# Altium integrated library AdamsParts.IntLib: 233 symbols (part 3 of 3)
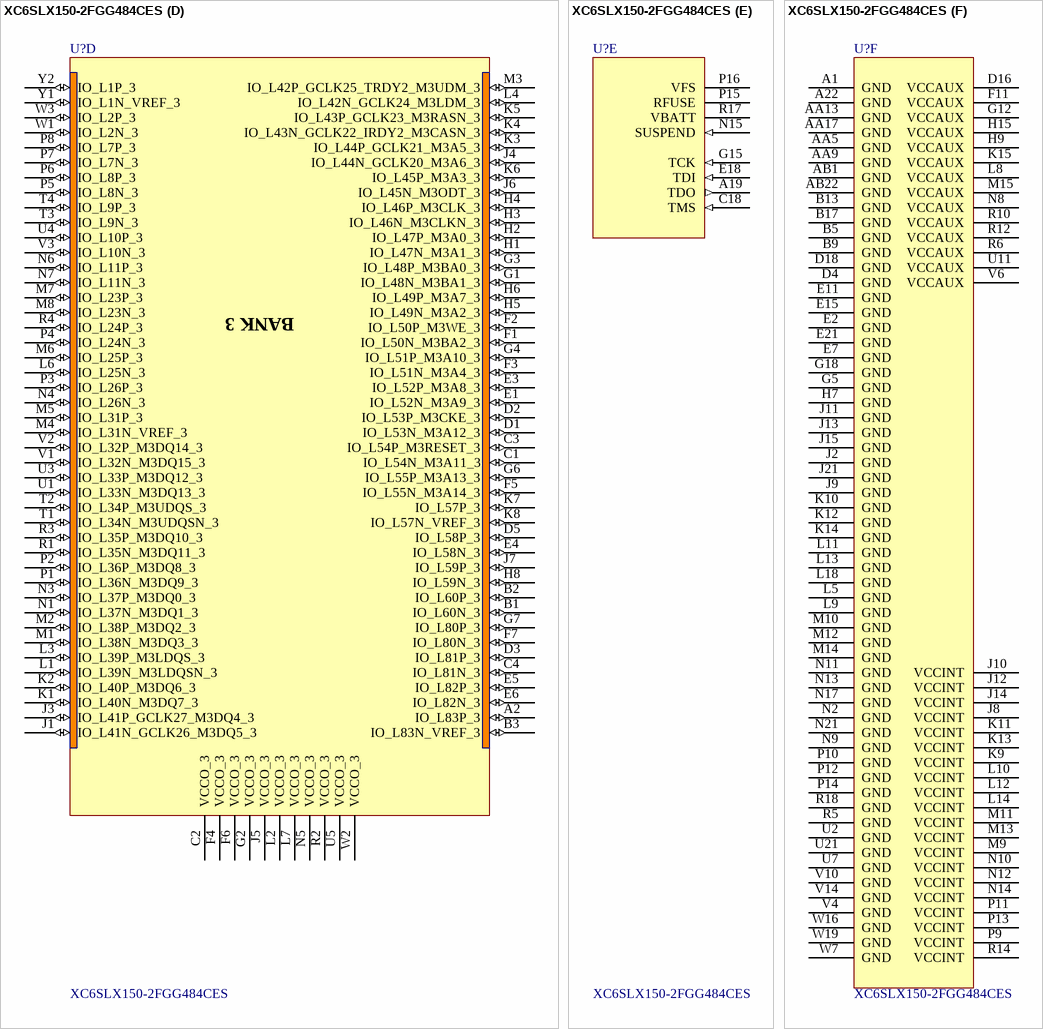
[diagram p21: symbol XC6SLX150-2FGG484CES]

## XC6SLX150-2FGG484CES
designator U?
Spartan 6 LX150 FGG484; Manufacturer: Xilinx
footprint FGG484 (BGA, 484-Leads, Body 23x23mm, Pitch 1mm)
part A pins: A3 IO_L1P_HSWAPEN_0 (io), A4 IO_L1N_VREF_0 (io), A5 IO_L2N_0 (io), A6 IO_L4N_0 (io), A7 IO_L5N_0 (io), A8 IO_L6N_0 (io), A9 IO_L8N_VREF_0 (io), A10 IO_L34N_GCLK18_0 (io), A11 IO_L35N_GCLK16_0 (io), A12 IO_L37N_GCLK12_0 (io), A13 IO_L38N_VREF_0 (io), A14 IO_L50N_0 (io), A15 IO_L51N_0 (io), A16 IO_L63N_SCP6_0 (io), A17 IO_L64N_SCP4_0 (io), A18 IO_L65N_SCP2_0 (io), B4 VCCO_0 (power), B6 IO_L4P_0 (io), B7 VCCO_0 (power), B8 IO_L6P_0 (io), B10 IO_L34P_GCLK19_0 (io), B11 VCCO_0 (power), B12 IO_L37P_GCLK13_0 (io), B14 IO_L50P_0 (io), B15 VCCO_0 (power), B16 IO_L63P_SCP7_0 (io), B18 IO_L65P_SCP3_0 (io), B19 VCCO_0 (power), C5 IO_L2P_0 (io), C6 IO_L3N_0 (io), C7 IO_L5P_0 (io), C8 IO_L7N_0 (io), C9 IO_L8P_0 (io), C10 IO_L33N_0 (io), C11 IO_L35P_GCLK17_0 (io), C12 IO_L36N_GCLK14_0 (io), C13 IO_L38P_0 (io), C14 IO_L49N_0 (io), C15 IO_L51P_0 (io), C16 IO_L62N_VREF_0 (io), C17 IO_L64P_SCP5_0 (io), D6 IO_L3P_0 (io), D7 IO_L32P_0 (io), D8 IO_L32N_0 (io), D9 IO_L7P_0 (io), D10 IO_L33P_0 (io), D11 IO_L36P_GCLK15_0 (io), D12 IO_L43N_0_AVOID (io), D13 IO_L45N_0_AVOID (io), D14 IO_L49P_0 (io), D15 IO_L62P_0 (io), D17 IO_L66N_SCP0_0 (io), E8 IO_L14P_0_AVOID (io), E9 VCCO_0 (power), E10 IO_L17P_0_AVOID (io), E12 IO_L43P_0_AVOID (io), E13 VCCO_0 (power), E14 IO_L47P_0_AVOID (io), E16 IO_L66P_SCP1_0 (io), E17 VCCO_0 (power), F8 IO_L14N_0_AVOID (io), F9 IO_L15N_0_AVOID (io), F10 IO_L17N_0_AVOID (io), F12 IO_L44N_0_AVOID (io), F13 IO_L45P_0_AVOID (io), F14 IO_L48P_0_AVOID (io), F15 IO_L47N_0_AVOID (io), G8 IO_L15P_0_AVOID (io), G9 IO_L16P_0_AVOID (io), G10 VCCO_0 (power), G11 IO_L18P_0_AVOID (io), G13 IO_L46N_0_AVOID (io), G14 VCCO_0 (power), H10 IO_L16N_0_AVOID (io), H11 IO_L18N_0_AVOID (io), H12 IO_L44P_0_AVOID (io), H13 IO_L46P_0_AVOID (io), H14 IO_L48N_0_AVOID (io)
part B pins: A20 IO_L20P_1 (io), A21 IO_L20N_1 (io), B20 IO_L1N_A24_VREF_1 (io), B21 IO_L19P_1 (io), B22 IO_L19N_1 (io), C19 IO_L1P_A25_1 (io), C20 IO_L32P_A17_M1A8_1 (io), C21 VCCO_1 (power), C22 IO_L32N_A16_M1A9_1 (io), D19 IO_L29P_A23_M1A13_1 (io), D20 IO_L29N_A22_M1A14_1 (io), D21 IO_L31P_A19_M1CKE_1 (io), D22 IO_L31N_A18_M1A12_1 (io), E19 VCCO_1 (power), E20 IO_L35P_A11_M1A7_1 (io), E22 IO_L35N_A10_M1A2_1 (io), F16 IO_L10P_1 (io), F17 IO_L10N_1 (io), F18 IO_L30P_A21_M1RESET_1 (io), F19 IO_L30N_A20_M1A11_1 (io), F20 IO_L33N_A14_M1A4_1 (io), F21 IO_L37P_A7_M1A0_1 (io), F22 IO_L37N_A6_M1A1_1 (io), G16 IO_L9P_1 (io), G17 IO_L9N_1 (io), G19 IO_L33P_A15_M1A10_1 (io), G20 IO_L39P_M1A3_1 (io), G21 VCCO_1 (power), G22 IO_L39N_M1ODT_1 (io), H16 IO_L28P_1 (io), H17 IO_L28N_VREF_1 (io), H18 IO_L34N_A12_M1BA2_1 (io), H19 IO_L34P_A13_M1WE_1 (io), H20 IO_L38P_A5_M1CLK_1 (io), H21 IO_L41P_GCLK9_IRDY1_M1RASN_1 (io), H22 IO_L41N_GCLK8_M1CASN_1 (io), J16 IO_L21N_1 (io), J17 IO_L36P_A9_M1BA0_1 (io), J18 VCCO_1 (power), J19 IO_L38N_A4_M1CLKN_1 (io), J20 IO_L43P_GCLK5_M1DQ4_1 (io), J22 IO_L43N_GCLK4_M1DQ5_1 (io), K16 IO_L21P_1 (io), K17 IO_L36N_A8_M1BA1_1 (io), K18 IO_L61N_1 (io), K19 IO_L40N_GCLK10_M1A6_1 (io), K20 IO_L40P_GCLK11_M1A5_1 (io), K21 IO_L44P_A3_M1DQ6_1 (io), K22 IO_L44N_A2_M1DQ7_1 (io), L15 IO_L58N_1 (io), L16 VCCO_1 (power), L17 IO_L61P_1 (io), L19 IO_L42N_GCLK6_TRDY1_M1LDM_1 (io), L20 IO_L45P_A1_M1LDQS_1 (io), L21 VCCO_1 (power), L22 IO_L45N_A0_M1LDQSN_1 (io), M16 IO_L58P_1 (io), M17 IO_L71P_1 (io), M18 IO_L71N_1 (io), M19 IO_L53P_1 (io), M20 IO_L42P_GCLK7_M1UDM_1 (io), M21 IO_L46P_FCS_B_M1DQ2_1 (io), M22 IO_L46N_FOE_B_M1DQ3_1 (io), N16 IO_L72N_1 (io), N18 VCCO_1 (power), N19 IO_L53N_VREF_1 (io), N20 IO_L47P_FWE_B_M1DQ0_1 (io), N22 IO_L47N_LDC_M1DQ1_1 (io), P17 IO_L72P_1 (io), P18 IO_L73P_1 (io), P19 IO_L59P_1 (io), P20 IO_L59N_1 (io), P21 IO_L48P_HDC_M1DQ8_1 (io), P22 IO_L48N_M1DQ9_1 (io), R19 IO_L73N_1 (io), R20 IO_L49P_M1DQ10_1 (io), R21 VCCO_1 (power), R22 IO_L49N_M1DQ11_1 (io), T19 IO_L74P_AWAKE_1 (io), T20 IO_L74N_DOUT_BUSY_1 (io), T21 IO_L50P_M1UDQS_1 (io), T22 IO_L50N_M1UDQSN_1 (io), U18 VCCO_1 (power), U19 IO_L70P_1 (io), U20 IO_L51P_M1DQ12_1 (io), U22 IO_L51N_M1DQ13_1 (io), V20 IO_L70N_1 (io), V21 IO_L52P_M1DQ14_1 (io), V22 IO_L52N_M1DQ15_1 (io), W20 IO_L60P_1 (io), W21 VCCO_1 (power), W22 IO_L60N_1 (io)
part C pins: AA1 PROGRAM_B_2 (io), AA2 IO_L64P_D8_2 (io), AA3 VCCO_2 (power), AA4 IO_L57P_2 (io), AA6 IO_L49P_D3_2 (io), AA7 VCCO_2 (power), AA8 IO_L45P_2 (io), AA10 IO_L41P_2 (io), AA11 VCCO_2 (power), AA12 IO_L31P_GCLK31_D14_2 (io), AA14 IO_L16P_2 (io), AA15 VCCO_2 (power), AA16 IO_L19P_2 (io), AA18 IO_L14P_D11_2 (io), AA19 VCCO_2 (power), AA20 IO_L3P_D0_DIN_MISO_MISO1_2 (io), AA21 IO_L2P_CMPCLK_2 (io), AA22 IO_L1N_M0_CMPMISO_2 (io), AB2 IO_L64N_D9_2 (io), AB3 IO_L58N_2 (io), AB4 IO_L57N_2 (io), AB5 IO_L54N_2_AVOID (io), AB6 IO_L49N_D4_2 (io), AB7 IO_L48N_RDWR_B_VREF_2 (io), AB8 IO_L45N_2 (io), AB9 IO_L43N_2 (io), AB10 IO_L41N_VREF_2 (io), AB11 IO_L32N_GCLK28_2 (io), AB12 IO_L31N_GCLK30_D15_2 (io), AB13 IO_L30N_GCLK0_USERCCLK_2 (io), AB14 IO_L16N_VREF_2 (io), AB15 IO_L21N_2 (io), AB16 IO_L19N_2 (io), AB17 IO_L15N_2 (io), AB18 IO_L14N_D12_2 (io), AB19 IO_L5N_2 (io), AB20 IO_L3N_MOSI_CSI_B_MISO0_2 (io), AB21 IO_L2N_CMPMOSI_2 (io), R7 IO_L60N_2_AVOID (io), R8 IO_L59N_2_AVOID (io), R9 IO_L59P_2_AVOID (io), R11 IO_L40P_2_AVOID (io), R13 IO_L23N_2_AVOID (io), R15 IO_L10N_2_AVOID (io), R16 IO_L10P_2_AVOID (io), T5 IO_L65N_CSO_B_2 (io), T6 IO_L65P_INIT_B_2 (io), T7 IO_L60P_2_AVOID (io), T8 IO_L51P_2_AVOID (io), T9 VCCO_2 (power), T10 IO_L52P_2_AVOID (io), T11 IO_L40N_2_AVOID (io), T12 IO_L22P_2_AVOID (io), T13 VCCO_2 (power), T14 IO_L23P_2_AVOID (io), T15 IO_L7N_2_AVOID (io), T16 IO_L7P_2_AVOID (io), T17 IO_L4N_VREF_2 (io), T18 IO_L4P_2 (io), U6 IO_L63P_2_AVOID (io), U8 IO_L51N_2_AVOID (io), U9 IO_L50P_2_AVOID (io), U10 IO_L52N_2_AVOID (io), U12 IO_L22N_2_AVOID (io), U13 IO_L12N_D2_MISO3_2 (io), U14 IO_L12P_D1_MISO2_2 (io), U15 IO_L13P_M1_2 (io), U16 IO_L8N_2_AVOID (io), U17 IO_L8P_2_AVOID (io), V5 IO_L63N_2_AVOID (io), V7 IO_L46N_2_AVOID (io), V8 VCCO_2 (power), V9 IO_L50N_2_AVOID (io), V11 IO_L42P_2 (io), V12 VCCO_2 (power), V13 IO_L18P_2_AVOID (io), V15 IO_L13N_D10_2 (io), V16 VCCO_2 (power), V17 IO_L11P_2_AVOID (io), V18 IO_L9N_2_AVOID (io), V19 IO_L9P_2_AVOID (io), W4 IO_L62P_D5_2 (io), W5 VCCO_2 (power), W6 IO_L53P_2_AVOID (io), W8 IO_L46P_2_AVOID (io), W9 IO_L47P_2_AVOID (io), W10 IO_L44P_2_AVOID (io), W11 IO_L42N_2 (io), W12 IO_L29P_GCLK3_2 (io), W13 IO_L18N_2_AVOID (io), W14 IO_L20P_2_AVOID (io), W15 IO_L17N_2_AVOID (io), W17 IO_L11N_2_AVOID (io), W18 IO_L6P_2_AVOID (io), Y3 IO_L58P_2 (io), Y4 IO_L62N_D6_2 (io), Y5 IO_L54P_2_AVOID (io), Y6 IO_L53N_2_AVOID (io), Y7 IO_L48P_D7_2 (io), Y8 IO_L47N_2_AVOID (io), Y9 IO_L43P_2 (io), Y10 IO_L44N_2_AVOID (io), Y11 IO_L32P_GCLK29_2 (io), Y12 IO_L29N_GCLK2_2 (io), Y13 IO_L30P_GCLK1_D13_2 (io), Y14 IO_L20N_2_AVOID (io), Y15 IO_L21P_2 (io), Y16 IO_L17P_2_AVOID (io), Y17 IO_L15P_2 (io), Y18 IO_L6N_2_AVOID (io), Y19 IO_L5P_2 (io), Y20 CMPCS_B_2 (io), Y21 IO_L1P_CCLK_2 (io), Y22 DONE_2 (io)
part D pins: A2 IO_L83P_3 (io), B1 IO_L60N_3 (io), B2 IO_L60P_3 (io), B3 IO_L83N_VREF_3 (io), C1 IO_L54N_M3A11_3 (io), C2 VCCO_3 (power), C3 IO_L54P_M3RESET_3 (io), C4 IO_L81N_3 (io), D1 IO_L53N_M3A12_3 (io), D2 IO_L53P_M3CKE_3 (io), D3 IO_L81P_3 (io), D5 IO_L58P_3 (io), E1 IO_L52N_M3A9_3 (io), E3 IO_L52P_M3A8_3 (io), E4 IO_L58N_3 (io), E5 IO_L82P_3 (io), E6 IO_L82N_3 (io), F1 IO_L50N_M3BA2_3 (io), F2 IO_L50P_M3WE_3 (io), F3 IO_L51N_M3A4_3 (io), F4 VCCO_3 (power), F5 IO_L55N_M3A14_3 (io), F6 VCCO_3 (power), F7 IO_L80N_3 (io), G1 IO_L48N_M3BA1_3 (io), G2 VCCO_3 (power), G3 IO_L48P_M3BA0_3 (io), G4 IO_L51P_M3A10_3 (io), G6 IO_L55P_M3A13_3 (io), G7 IO_L80P_3 (io), H1 IO_L47N_M3A1_3 (io), H2 IO_L47P_M3A0_3 (io), H3 IO_L46N_M3CLKN_3 (io), H4 IO_L46P_M3CLK_3 (io), H5 IO_L49N_M3A2_3 (io), H6 IO_L49P_M3A7_3 (io), H8 IO_L59N_3 (io), J1 IO_L41N_GCLK26_M3DQ5_3 (io), J3 IO_L41P_GCLK27_M3DQ4_3 (io), J4 IO_L44N_GCLK20_M3A6_3 (io), J5 VCCO_3 (power), J6 IO_L45N_M3ODT_3 (io), J7 IO_L59P_3 (io), K1 IO_L40N_M3DQ7_3 (io), K2 IO_L40P_M3DQ6_3 (io), K3 IO_L44P_GCLK21_M3A5_3 (io), K4 IO_L43N_GCLK22_IRDY2_M3CASN_3 (io), K5 IO_L43P_GCLK23_M3RASN_3 (io), K6 IO_L45P_M3A3_3 (io), K7 IO_L57P_3 (io), K8 IO_L57N_VREF_3 (io), L1 IO_L39N_M3LDQSN_3 (io), L2 VCCO_3 (power), L3 IO_L39P_M3LDQS_3 (io), L4 IO_L42N_GCLK24_M3LDM_3 (io), L6 IO_L25N_3 (io), L7 VCCO_3 (power), M1 IO_L38N_M3DQ3_3 (io), M2 IO_L38P_M3DQ2_3 (io), M3 IO_L42P_GCLK25_TRDY2_M3UDM_3 (io), M4 IO_L31N_VREF_3 (io), M5 IO_L31P_3 (io), M6 IO_L25P_3 (io), M7 IO_L23P_3 (io), M8 IO_L23N_3 (io), N1 IO_L37N_M3DQ1_3 (io), N3 IO_L37P_M3DQ0_3 (io), N4 IO_L26N_3 (io), N5 VCCO_3 (power), N6 IO_L11P_3 (io), N7 IO_L11N_3 (io), P1 IO_L36N_M3DQ9_3 (io), P2 IO_L36P_M3DQ8_3 (io), P3 IO_L26P_3 (io), P4 IO_L24N_3 (io), P5 IO_L8N_3 (io), P6 IO_L8P_3 (io), P7 IO_L7N_3 (io), P8 IO_L7P_3 (io), R1 IO_L35N_M3DQ11_3 (io), R2 VCCO_3 (power), R3 IO_L35P_M3DQ10_3 (io), R4 IO_L24P_3 (io), T1 IO_L34N_M3UDQSN_3 (io), T2 IO_L34P_M3UDQS_3 (io), T3 IO_L9N_3 (io), T4 IO_L9P_3 (io), U1 IO_L33N_M3DQ13_3 (io), U3 IO_L33P_M3DQ12_3 (io), U4 IO_L10P_3 (io), U5 VCCO_3 (power), V1 IO_L32N_M3DQ15_3 (io), V2 IO_L32P_M3DQ14_3 (io), V3 IO_L10N_3 (io), W1 IO_L2N_3 (io), W2 VCCO_3 (power), W3 IO_L2P_3 (io), Y1 IO_L1N_VREF_3 (io), Y2 IO_L1P_3 (io)
part E pins: A19 TDO (out), C18 TMS (in), E18 TDI (in), G15 TCK (in), N15 SUSPEND (in), P15 RFUSE, P16 VFS (power), R17 VBATT (power)
part F pins: A1 GND (power), A22 GND (power), AA5 GND (power), AA9 GND (power), AA13 GND (power), AA17 GND (power), AB1 GND (power), AB22 GND (power), B5 GND (power), B9 GND (power), B13 GND (power), B17 GND (power), D4 GND (power), D16 VCCAUX (power), D18 GND (power), E2 GND (power), E7 GND (power), E11 GND (power), E15 GND (power), E21 GND (power), F11 VCCAUX (power), G5 GND (power), G12 VCCAUX (power), G18 GND (power), H7 GND (power), H9 VCCAUX (power), H15 VCCAUX (power), J2 GND (power), J8 VCCINT (power), J9 GND (power), J10 VCCINT (power), J11 GND (power), J12 VCCINT (power), J13 GND (power), J14 VCCINT (power), J15 GND (power), J21 GND (power), K9 VCCINT (power), K10 GND (power), K11 VCCINT (power), K12 GND (power), K13 VCCINT (power), K14 GND (power), K15 VCCAUX (power), L5 GND (power), L8 VCCAUX (power), L9 GND (power), L10 VCCINT (power), L11 GND (power), L12 VCCINT (power), L13 GND (power), L14 VCCINT (power), L18 GND (power), M9 VCCINT (power), M10 GND (power), M11 VCCINT (power), M12 GND (power), M13 VCCINT (power), M14 GND (power), M15 VCCAUX (power), N2 GND (power), N8 VCCAUX (power), N9 GND (power), N10 VCCINT (power), N11 GND (power), N12 VCCINT (power), N13 GND (power), N14 VCCINT (power), N17 GND (power), N21 GND (power), P9 VCCINT (power), P10 GND (power), P11 VCCINT (power), P12 GND (power), P13 VCCINT (power), P14 GND (power), R5 GND (power), R6 VCCAUX (power), R10 VCCAUX (power), R12 VCCAUX (power), R14 VCCINT (power), R18 GND (power), U2 GND (power), U7 GND (power), U11 VCCAUX (power), U21 GND (power), V4 GND (power), V6 VCCAUX (power), V10 GND (power), V14 GND (power), W7 GND (power), W16 GND (power), W19 GND (power)

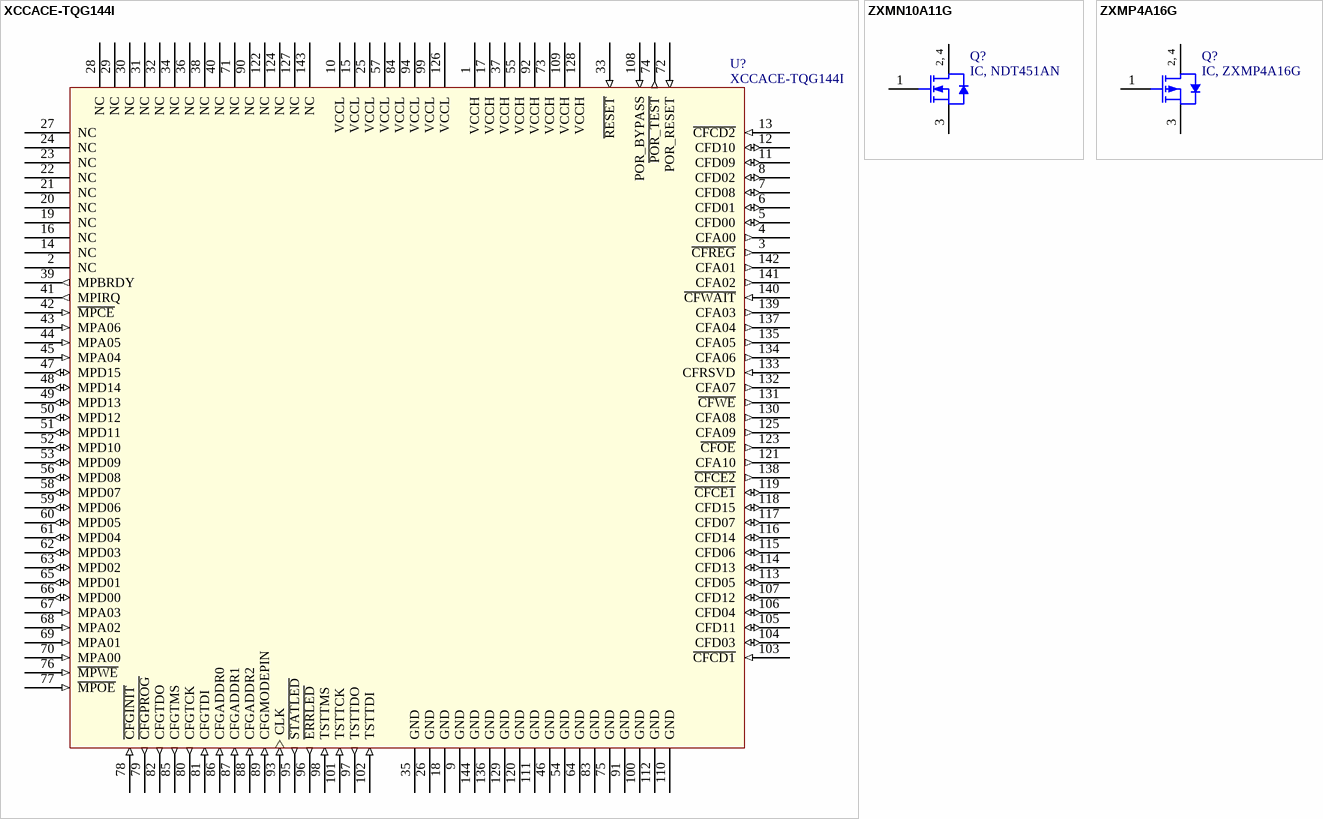
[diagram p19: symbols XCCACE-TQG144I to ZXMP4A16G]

## XCCACE-TQG144I
designator U?
System ACE CF Xilinx
footprint TQFP144 (144-Pin Plastic Thin Quad Flat Pack (TQFP))
pins: 1 VCCH (power), 2 NC, 3 ~{CFREG} (out), 4 CFA00 (out), 5 CFD00 (io), 6 CFD01 (io), 7 CFD08 (io), 8 CFD02 (io), 9 GND (power), 10 VCCL (power), 11 CFD09 (io), 12 CFD10 (io), 13 ~{CFCD2} (in), 14 NC, 15 VCCL (power), 16 NC, 17 VCCH (power), 18 GND (power), 19 NC, 20 NC, 21 NC, 22 NC, 23 NC, 24 NC, 25 VCCL (power), 26 GND (power), 27 NC, 28 NC, 29 NC, 30 NC, 31 NC, 32 NC, 33 ~{RESET} (in), 34 NC, 35 GND (power), 36 NC, 37 VCCH (power), 38 NC, 39 MPBRDY (out), 40 NC, 41 MPIRQ (out), 42 ~{MPCE} (in), 43 MPA06 (in), 44 MPA05 (in), 45 MPA04 (in), 46 GND (power), 47 MPD15 (io), 48 MPD14 (io), 49 MPD13 (io), 50 MPD12 (io), 51 MPD11 (io), 52 MPD10 (io), 53 MPD09 (io), 54 GND (power), 55 VCCH (power), 56 MPD08 (io), 57 VCCL (power), 58 MPD07 (io), 59 MPD06 (io), 60 MPD05 (io), 61 MPD04 (io), 62 MPD03 (io), 63 MPD02 (io), 64 GND (power), 65 MPD01 (io), 66 MPD00 (io), 67 MPA03 (in), 68 MPA02 (in), 69 MPA01 (in), 70 MPA00 (in), 71 NC, 72 POR_RESET (in), 73 VCCH (power), 74 ~{POR_TEST} (out), 75 GND (power), 76 ~{MPWE} (in), 77 ~{MPOE} (in), 78 ~{CFGINIT} (in), 79 ~{CFGPROG} (out), 80 CFGTCK (out), 81 CFGTDI (in), 82 CFGTDO (out), 83 GND (power), 84 VCCL (power), 85 CFGTMS (out), 86 CFGADDR0 (in), 87 CFGADDR1 (in), 88 CFGADDR2 (in), 89 CFGMODEPIN (in), 90 NC, 91 GND (power), 92 VCCH (power), 93 CLK (in), 94 VCCL (power), 95 ~{STATLED} (out), 96 ~{ERRLED} (out), 97 TSTTDO (out), 98 TSTTMS (in), 99 VCCL (power), 100 GND (power), 101 TSTTCK (in), 102 TSTTDI (in), 103 ~{CFCD1} (in), 104 CFD03 (io), 105 CFD11 (io), 106 CFD04 (io), 107 CFD12 (io), 108 POR_BYPASS (in), 109 VCCH (power), 110 GND (power), 111 GND (power), 112 GND (power), 113 CFD05 (io), 114 CFD13 (io), 115 CFD06 (io), 116 CFD14 (io), 117 CFD07 (io), 118 CFD15 (io), 119 ~{CFCE1} (io), 120 GND (power), 121 CFA10 (out), 122 NC, 123 ~{CFOE} (out), 124 NC, 125 CFA09 (out), 126 VCCL (power), 127 NC, 128 VCCH (power), 129 GND (power), 130 CFA08 (out), 131 ~{CFWE} (out), 132 CFA07 (out), 133 CFRSVD (in), 134 CFA06 (out), 135 CFA05 (out), 136 GND (power), 137 CFA04 (out), 138 ~{CFCE2} (out), 139 CFA03 (out), 140 ~{CFWAIT} (in), 141 CFA02 (out), 142 CFA01 (out), 143 NC, 144 GND (power)

## ZXMN10A11G
designator Q?, comment IC, NDT451AN
100V N-Channel Enhancement Mode MOSFET; PackageDocument: 2002
footprint SOT223 (SOT-223/SC-73; 4 Leads; Body 6.7 x 7.3 mm, inc. leads (LxW max))
pins: 1 G, 2 D, 3 S, 4 D

## ZXMP4A16G
designator Q?, comment IC, ZXMP4A16G
40V P-Channel Enhancement Mode MOSFET; PackageDocument: 2002
footprint SOT223 (SOT-223/SC-73; 4 Leads; Body 6.7 x 7.3 mm, inc. leads (LxW max))
pins: 1 G, 2 D, 3 S, 4 D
